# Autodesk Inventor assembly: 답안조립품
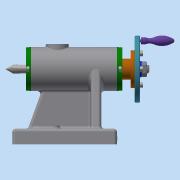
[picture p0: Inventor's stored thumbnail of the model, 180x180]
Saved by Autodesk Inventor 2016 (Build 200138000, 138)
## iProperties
Created: 2022-06
Part Number: 답안조립품
Material: 일반
Document SubType Name: Assembly
Designer: PC-1-3
Author: PC-1-3
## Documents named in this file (18)
- C:\Users\PC-1-3\Desktop\720606V1017\답안조립품.iam
- C:\Users\PC-1-3\Desktop\720606V1017\본체.ipt
- C:\Users\PC-1-3\Desktop\720606V1017\슬리브.ipt
- C:\Users\PC-1-3\Desktop\720606V1017\중공축.ipt
- C:\Users\PC-1-3\Desktop\720606V1017\센터홀더.ipt
- C:\Users\PC-1-3\Desktop\720606V1017\멈춤나사 M3.ipt
- C:\Users\PC-1-3\Desktop\720606V1017\센터.ipt
- C:\Users\PC-1-3\Desktop\720606V1017\부시.ipt
- C:\Users\PC-1-3\Desktop\720606V1017\커버.ipt
- C:\Users\PC-1-3\Desktop\720606V1017\나사축.ipt
- C:\Users\PC-1-3\Desktop\720606V1017\키 4 x 4 x 10.ipt
- C:\Users\PC-1-3\Desktop\720606V1017\플랜지.ipt
- C:\Users\PC-1-3\Desktop\720606V1017\돌림판.ipt
- C:\Users\PC-1-3\Desktop\720606V1017\와셔.ipt
- C:\Users\PC-1-3\Desktop\720606V1017\너트 M8.ipt
- C:\Users\PC-1-3\Desktop\720606V1017\핸들.ipt
- C:\Users\PC-1-3\Desktop\720606V1017\나사.ipt
- C:\Users\PC-1-3\Desktop\720606V1017\볼트 M3.ipt
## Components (2 placed, 2 different names)
1. 플랜지:1
2. 핸들:1
